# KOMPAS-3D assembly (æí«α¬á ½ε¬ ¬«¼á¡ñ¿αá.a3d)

Referenced files in D:\МОДЕЛЬ ТАНКА Т90\ДЕТАЛИ\БАШНЯ\башня сварная\: люк командира основание.m3d, люк командира.m3d, пквт.m3d, Сборка каробка патрон.a3d, тяга кпвт.m3d
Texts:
  Сборка люк командира
  stalker61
